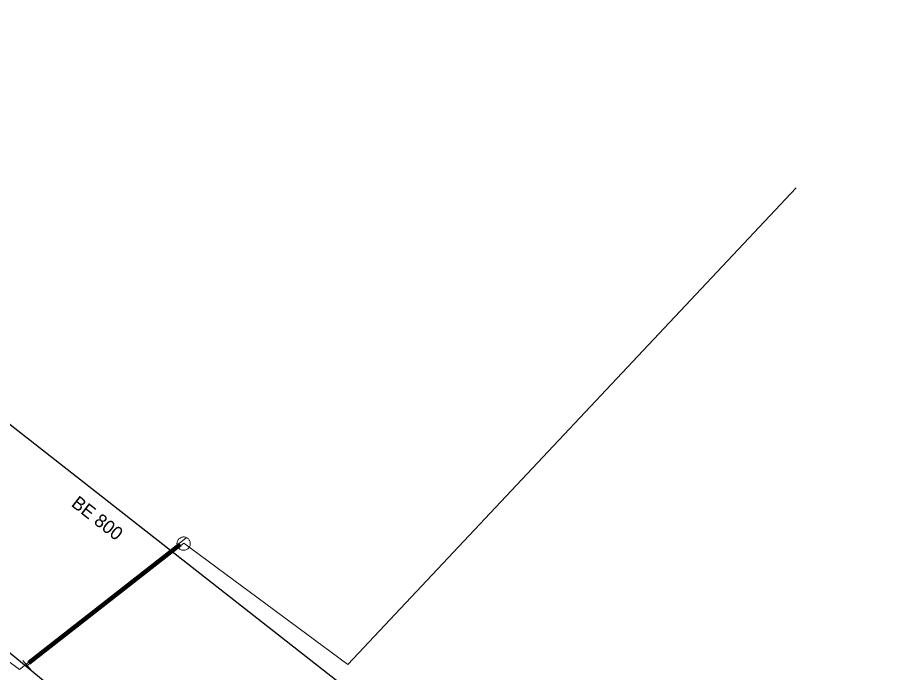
# Model space of a CAD drawing. Extents: x -807203 to -805207, y -993656 to -992505.
# Drawn here: x -806201.1 to -806136.1, y -993114.2 to -993064.8 of the extents above; entities that cross this region are included whole.
import ezdxf

# ---------------------------------------------------------------- set-up
doc = ezdxf.new("R2010")
doc.units = 0
doc.header["$LTSCALE"] = 0.4
for name, color, linetype, lineweight in [('1', 7, 'Continuous', 13), ('13', 7, 'Continuous', 13), ('14', 7, 'Continuous', 25), ('17', 7, 'Continuous', 25), ('23', 7, 'Continuous', 13), ('3', 7, 'Continuous', 106), ('34', 7, 'Continuous', 13)]:
    doc.layers.add(name, color=color, linetype=linetype, lineweight=lineweight)

msp = doc.modelspace()

# ---------------------------------------------------------------- linework, layer by layer
at = {"layer": '13'}
msp.add_line((-806200.361, -993113.627), (-806188.589, -993104.418), dxfattribs=at)
for points in [[(-806188.589, -993104.418), (-806176.225, -993113.561), (-806142.49, -993077.676)], [(-806208.673, -993107.877), (-806208.857, -993108.048), (-806200.958, -993113.93), (-806188.421, -993104.047)]]:
    msp.add_lwpolyline(points, dxfattribs=at)
at = {"layer": '14', "lineweight": 13}
msp.add_line((-806200.433, -993113.675), (-806200.361, -993113.627), dxfattribs=at)
at = {"layer": '14'}
msp.add_lwpolyline([(-806213.75, -993086.03), (-806174.365, -993116.849), (-806173.301, -993117.667)], dxfattribs=at)
at = {"layer": '17'}
msp.add_lwpolyline([(-806260.066, -993064.828), (-806248.392, -993074.528), (-806229.53, -993089.861), (-806208.251, -993107.276), (-806200.433, -993113.675), (-806198.425, -993115.318), (-806170.996, -993137.161), (-806169.414, -993138.403), (-806155.574, -993149.442), (-806086.497, -993204.202), (-806063.424, -993223.055)], dxfattribs=at)
at = {"layer": '23'}
for points in [[(-806188.202, -993104.137), (-806188.237, -993104.097), (-806188.276, -993104.062), (-806188.318, -993104.033), (-806188.363, -993104.006), (-806188.411, -993103.984), (-806188.461, -993103.968), (-806188.512, -993103.957), (-806188.563, -993103.951), (-806188.616, -993103.951), (-806188.668, -993103.956), (-806188.72, -993103.966), (-806188.77, -993103.982), (-806188.817, -993104.003), (-806188.862, -993104.029), (-806188.905, -993104.059), (-806188.945, -993104.095), (-806188.979, -993104.132), (-806189.011, -993104.176), (-806189.037, -993104.219), (-806189.059, -993104.267), (-806189.075, -993104.319), (-806189.086, -993104.369), (-806189.092, -993104.422), (-806189.093, -993104.474), (-806189.087, -993104.525), (-806189.076, -993104.577), (-806189.06, -993104.626), (-806189.039, -993104.674), (-806189.013, -993104.719), (-806188.983, -993104.762), (-806188.948, -993104.801), (-806188.909, -993104.837), (-806188.867, -993104.868), (-806188.822, -993104.894), (-806188.775, -993104.914), (-806188.725, -993104.931), (-806188.674, -993104.943), (-806188.621, -993104.949), (-806188.569, -993104.949)], [(-806188.569, -993104.949), (-806188.518, -993104.944), (-806188.466, -993104.933), (-806188.416, -993104.918), (-806188.368, -993104.896), (-806188.324, -993104.87), (-806188.281, -993104.84), (-806188.242, -993104.805), (-806188.206, -993104.767), (-806188.175, -993104.724), (-806188.149, -993104.679), (-806188.127, -993104.631), (-806188.11, -993104.582), (-806188.1, -993104.53), (-806188.093, -993104.479), (-806188.094, -993104.427), (-806188.098, -993104.374), (-806188.109, -993104.323), (-806188.125, -993104.273), (-806188.147, -993104.225), (-806188.172, -993104.18), (-806188.202, -993104.137), (-806188.237, -993104.097), (-806188.276, -993104.062), (-806188.318, -993104.033), (-806188.363, -993104.006), (-806188.411, -993103.984), (-806188.461, -993103.968), (-806188.512, -993103.957), (-806188.563, -993103.951), (-806188.616, -993103.951), (-806188.668, -993103.956), (-806188.72, -993103.966), (-806188.77, -993103.982), (-806188.817, -993104.003), (-806188.862, -993104.029), (-806188.905, -993104.059), (-806188.945, -993104.095), (-806188.979, -993104.132), (-806189.011, -993104.176)], [(-806189.011, -993104.176), (-806189.037, -993104.219), (-806189.059, -993104.267), (-806189.075, -993104.319), (-806189.086, -993104.369), (-806189.092, -993104.422), (-806189.093, -993104.474), (-806189.087, -993104.525), (-806189.076, -993104.577), (-806189.06, -993104.626), (-806189.039, -993104.674), (-806189.013, -993104.719), (-806188.983, -993104.762), (-806188.948, -993104.801), (-806188.909, -993104.837), (-806188.867, -993104.868), (-806188.822, -993104.894), (-806188.775, -993104.914), (-806188.725, -993104.931), (-806188.674, -993104.943), (-806188.621, -993104.949), (-806188.569, -993104.949), (-806188.518, -993104.944), (-806188.466, -993104.933), (-806188.416, -993104.918), (-806188.368, -993104.896), (-806188.324, -993104.87), (-806188.281, -993104.84), (-806188.242, -993104.805), (-806188.206, -993104.767), (-806188.175, -993104.724), (-806188.149, -993104.679), (-806188.127, -993104.631), (-806188.11, -993104.582), (-806188.1, -993104.53), (-806188.093, -993104.479), (-806188.094, -993104.427), (-806188.098, -993104.374), (-806188.109, -993104.323), (-806188.125, -993104.273)], [(-806188.125, -993104.273), (-806188.147, -993104.225), (-806188.172, -993104.18), (-806188.202, -993104.137)]]:
    msp.add_lwpolyline(points, dxfattribs=at)
at = {"layer": '3'}
msp.add_line((-806200.236, -993113.429), (-806188.852, -993104.52), dxfattribs=at)
at = {"layer": '3', "lineweight": 100}
msp.add_line((-806200.236, -993113.429), (-806188.852, -993104.52), dxfattribs=at)
at = {"layer": '34'}
msp.add_line((-806200.684, -993113.245), (-806200.038, -993114.009), dxfattribs=at)

# ---------------------------------------------------------------- texts
at = {"layer": '1'}
msp.add_text('BE 800', height=1, rotation=322, dxfattribs=at).set_placement((-806197.118, -993101.572))

doc.saveas('drawing.dxf')
